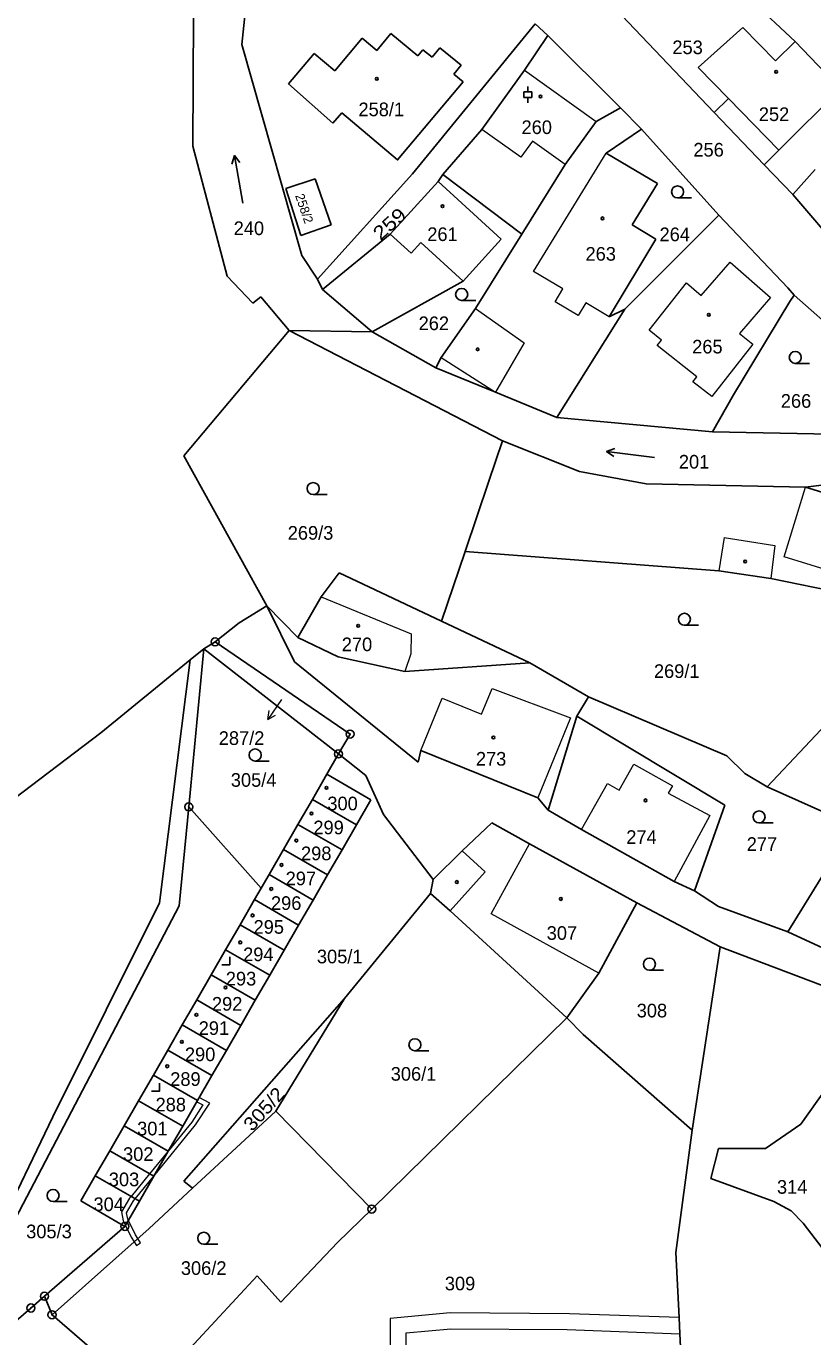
# Model space of a CAD drawing. Extents: x -727701 to -724405, y -960481 to -957284.
# Drawn here: x -727055.1 to -726957, y -958124 to -957960.6 of the extents above; entities that cross this region are included whole.
import ezdxf
from ezdxf.enums import TextEntityAlignment as Align

# ---------------------------------------------------------------- set-up
doc = ezdxf.new("R2010")
doc.units = 0
doc.header["$LTSCALE"] = 0.68
for name, color, linetype, lineweight in [('1', 7, 'Continuous', 25), ('13', 7, 'Continuous', 13), ('3', 7, 'Continuous', 25), ('4', 7, 'Continuous', 13), ('5', 7, 'Continuous', 25), ('7', 7, 'Continuous', 13), ('8', 7, 'Continuous', 25)]:
    doc.layers.add(name, color=color, linetype=linetype, lineweight=lineweight)
doc.layers.add('2', color=7, linetype='Continuous')

msp = doc.modelspace()

# ---------------------------------------------------------------- linework, layer by layer
at = {"layer": '1'}
for p, q in [((-727027.33, -957954.13), (-727028.21, -957962.91)), ((-726982.51, -957957.55), (-726969.33, -957971.38)), ((-726959.21, -957962.52), (-726964.74, -957957.39)), ((-727034.33, -957975.58), (-727034.25, -957959.25)), ((-727006.95, -957979.03), (-726991.64, -957960.34)), ((-726990.05, -957961.81), (-726991.64, -957960.34)), ((-727016.64, -957966.2), (-727013.22, -957962.12)), ((-727013.22, -957962.12), (-727011.39, -957963.67)), ((-727011.39, -957963.67), (-727009.64, -957961.55)), ((-727009.64, -957961.55), (-727006.26, -957964.34)), ((-726992.98, -957966.1), (-726990.05, -957961.81)), ((-726981, -957970.8), (-726990.05, -957961.81)), ((-726965.77, -957960.81), (-726971.31, -957965.77)), ((-726961.7, -957964.96), (-726965.77, -957960.81)), ((-727028.21, -957962.91), (-727020.72, -957989.23)), ((-727006.26, -957964.34), (-727005.64, -957963.56)), ((-727005.64, -957963.56), (-727004.47, -957964.49)), ((-727004.47, -957964.49), (-727003.54, -957963.33)), ((-727003.54, -957963.33), (-727000.86, -957965.47)), ((-726959.21, -957962.52), (-726961.7, -957964.96)), ((-726953.58, -957968.43), (-726959.21, -957962.52)), ((-727022.4, -957967.83), (-727019.21, -957964.04)), ((-727019.21, -957964.04), (-727016.64, -957966.2)), ((-727000.86, -957965.47), (-727001.79, -957966.63)), ((-727001.79, -957966.63), (-727000.63, -957967.56)), ((-726998.28, -957973.5), (-726992.98, -957966.1)), ((-726971.31, -957965.77), (-726967.55, -957969.64)), ((-727016.86, -957972.73), (-727022.4, -957967.83)), ((-726961.28, -957976.08), (-726953.58, -957968.43)), ((-726967.55, -957969.64), (-726969.33, -957971.38)), ((-727015.77, -957971.44), (-727016.86, -957972.73)), ((-726984.04, -957972.51), (-726981, -957970.8)), ((-726978.4, -957973.45), (-726981, -957970.8)), ((-726969.33, -957971.38), (-726963.11, -957977.91)), ((-727003.15, -957979.12), (-726998.28, -957973.5)), ((-726987.89, -957977.89), (-726984.04, -957972.51)), ((-726982.79, -957976.48), (-726978.4, -957973.45)), ((-726968.75, -957984.19), (-726978.4, -957973.45)), ((-727030.04, -957991.79), (-727034.33, -957975.58)), ((-726976.41, -957980.24), (-726982.79, -957976.48)), ((-726963.11, -957977.91), (-726961.28, -957976.08)), ((-726993.3, -957986.57), (-726987.89, -957977.89)), ((-726963.11, -957977.91), (-726959.51, -957981.63)), ((-727022.75, -957980.85), (-727019.06, -957979.65)), ((-727019.06, -957979.65), (-727017.1, -957985.39)), ((-727018.8, -957992.19), (-727006.95, -957979.03)), ((-727009.74, -957986.55), (-727003.76, -957979.99)), ((-727003.76, -957979.99), (-727003.15, -957979.12)), ((-726995.87, -957987.2), (-727003.76, -957979.99)), ((-727003.15, -957979.12), (-726993.3, -957986.57)), ((-726956.74, -957978.5), (-726959.51, -957981.63)), ((-727020.85, -957986.71), (-727022.75, -957980.85)), ((-726979.56, -957985.41), (-726976.41, -957980.24)), ((-726959.51, -957981.63), (-726950.42, -957992.25)), ((-726980.45, -957995.91), (-726968.75, -957984.19)), ((-726960.13, -957993.26), (-726968.75, -957984.19)), ((-727017.1, -957985.39), (-727020.85, -957986.71)), ((-727018.15, -957993.47), (-727009.74, -957986.55)), ((-726999.07, -957995.83), (-726993.3, -957986.57)), ((-726976.62, -957987.17), (-726979.56, -957985.41)), ((-727000.62, -957992.41), (-726995.87, -957987.2)), ((-726982.41, -957996.85), (-726976.62, -957987.17)), ((-727020.72, -957989.23), (-727018.8, -957992.19)), ((-727026.83, -957995.18), (-727030.04, -957991.79)), ((-727018.8, -957992.19), (-727018.15, -957993.47)), ((-727011.98, -957998.72), (-727000.62, -957992.41)), ((-727025.84, -957994.37), (-727026.83, -957995.18)), ((-727022.34, -957998.59), (-727025.84, -957994.37)), ((-727018.15, -957993.47), (-727011.98, -957998.72)), ((-726959.34, -957994.18), (-726960.13, -957993.26)), ((-726959.88, -957994.94), (-726959.34, -957994.18)), ((-726959.34, -957994.18), (-726949.18, -958003.2)), ((-727003.38, -958001.95), (-726999.07, -957995.83)), ((-726988.96, -958009.41), (-726980.45, -957995.91)), ((-726980.45, -957995.91), (-726982.41, -957996.85)), ((-726966.9, -958006.6), (-726959.88, -957994.94)), ((-727035.47, -958014.18), (-727022.34, -957998.59)), ((-727022.34, -957998.59), (-726995.72, -958012.31)), ((-727022.34, -957998.59), (-727011.98, -957998.72)), ((-727011.98, -957998.72), (-727004.05, -958003.22)), ((-727004.05, -958003.22), (-727003.38, -958001.95)), ((-727004.05, -958003.22), (-726996.59, -958006.28)), ((-726996.59, -958006.28), (-726988.96, -958009.41)), ((-726969.55, -958011.22), (-726966.9, -958006.6)), ((-726988.96, -958009.41), (-726969.55, -958011.22)), ((-726995.72, -958012.31), (-726997.43, -958017.36)), ((-726995.72, -958012.31), (-726986.13, -958016.16)), ((-726969.55, -958011.22), (-726954.77, -958011.5)), ((-727025.11, -958032.9), (-727035.47, -958014.18)), ((-726997.43, -958017.36), (-727000.39, -958026.11)), ((-726986.13, -958016.16), (-726977.8, -958017.71)), ((-726957.94, -958018.11), (-726942.44, -958016.08)), ((-726977.8, -958017.71), (-726957.94, -958018.11)), ((-726945.74, -958021.85), (-726957.94, -958018.11)), ((-727000.39, -958026.11), (-727003.33, -958034.81)), ((-726968.75, -958028.55), (-727000.39, -958026.11)), ((-727018.35, -958031.77), (-727016.1, -958028.8)), ((-727016.1, -958028.8), (-727003.33, -958034.81)), ((-726968.75, -958028.55), (-726962.25, -958029.5)), ((-726962.25, -958029.5), (-726950.05, -958032)), ((-727021.23, -958036.86), (-727018.35, -958031.77)), ((-727028.57, -958035.03), (-727025.11, -958032.9)), ((-727025.11, -958032.9), (-727021.23, -958036.86)), ((-727021.65, -958039.9), (-727025.11, -958032.9)), ((-727028.57, -958035.03), (-727031.55, -958037.4)), ((-727003.33, -958034.81), (-726992.3, -958040)), ((-727021.23, -958036.86), (-727016.19, -958039.26)), ((-727032.95, -958038.25), (-727034.84, -958057.97)), ((-727034.66, -958039.64), (-727032.95, -958038.25)), ((-727032.95, -958038.25), (-727031.55, -958037.4)), ((-727016.18, -958051.37), (-727032.95, -958038.25)), ((-727031.55, -958037.4), (-727014.73, -958048.89)), ((-726962.73, -958055.45), (-726946.89, -958038.61)), ((-727045.8, -958048.73), (-727034.66, -958039.64)), ((-727038.49, -958069.94), (-727034.66, -958039.64)), ((-727006.24, -958052.4), (-727021.65, -958039.9)), ((-727016.19, -958039.26), (-727007.91, -958041.08)), ((-727007.91, -958041.08), (-726992.3, -958040)), ((-726992.3, -958040), (-726984.99, -958044.25)), ((-726986.46, -958046.64), (-726984.99, -958044.25)), ((-726984.99, -958044.25), (-726967.76, -958051.62)), ((-726990.02, -958058.36), (-726986.46, -958046.64)), ((-726986.46, -958046.64), (-726967.99, -958057.74)), ((-727080.39, -958074.95), (-727045.8, -958048.73)), ((-727014.73, -958048.89), (-727016.18, -958051.37)), ((-727016.18, -958051.37), (-727017.64, -958053.88)), ((-727012.76, -958054.04), (-727016.18, -958051.37)), ((-727005.9, -958050.92), (-727006.24, -958052.4)), ((-726991.32, -958056.85), (-727005.9, -958050.92)), ((-726967.76, -958051.62), (-726965.5, -958053.82)), ((-727019.42, -958057.03), (-727017.64, -958053.88)), ((-727017.64, -958053.88), (-727012.12, -958057.08)), ((-727010.57, -958058.93), (-727012.76, -958054.04)), ((-726965.5, -958053.82), (-726962.73, -958055.45)), ((-726990.02, -958058.36), (-726991.32, -958056.85)), ((-726962.73, -958055.45), (-726953.06, -958059.81)), ((-727036.02, -958070.29), (-727034.84, -958057.97)), ((-727034.84, -958057.97), (-727025.81, -958068.11)), ((-727021.23, -958060.16), (-727019.42, -958057.03)), ((-727013.93, -958060.2), (-727019.42, -958057.03)), ((-727012.12, -958057.08), (-727013.93, -958060.2)), ((-726985.87, -958060.8), (-726990.02, -958058.36)), ((-726971.8, -958068.45), (-726967.99, -958057.74)), ((-727023.03, -958063.28), (-727021.23, -958060.16)), ((-727015.73, -958063.33), (-727021.23, -958060.16)), ((-727010.57, -958058.93), (-727004.36, -958067.03)), ((-726997.07, -958059.97), (-727000.76, -958063.46)), ((-726992.34, -958062.57), (-726997.07, -958059.97)), ((-727013.93, -958060.2), (-727015.73, -958063.33)), ((-726974.3, -958067.28), (-726985.87, -958060.8)), ((-727024.83, -958066.41), (-727023.03, -958063.28)), ((-727017.53, -958066.45), (-727023.03, -958063.28)), ((-727015.73, -958063.33), (-727017.53, -958066.45)), ((-726978.96, -958069.95), (-726992.34, -958062.57)), ((-727000.76, -958063.46), (-727004.36, -958067.03)), ((-726960.13, -958073.56), (-726954.24, -958063.98)), ((-727024.83, -958066.41), (-727025.81, -958068.11)), ((-727019.33, -958069.58), (-727024.83, -958066.41)), ((-727017.53, -958066.45), (-727019.33, -958069.58)), ((-727026.63, -958069.53), (-727025.81, -958068.11)), ((-727004.36, -958067.03), (-727004.71, -958068.75)), ((-726971.8, -958068.45), (-726974.3, -958067.28)), ((-727051.8, -958096.6), (-727038.49, -958069.94)), ((-727028.44, -958072.66), (-727026.63, -958069.53)), ((-727021.14, -958072.7), (-727026.63, -958069.53)), ((-727019.33, -958069.58), (-727021.14, -958072.7)), ((-727004.71, -958068.75), (-727015.4, -958081.85)), ((-727004.71, -958068.75), (-727002.26, -958070.94)), ((-726978.96, -958069.95), (-726983.73, -958078.71)), ((-726968.6, -958075.4), (-726978.96, -958069.95)), ((-726968.78, -958070.41), (-726971.8, -958068.45)), ((-727057.36, -958111.03), (-727036.02, -958070.29)), ((-727002.26, -958070.94), (-726987.71, -958084.26)), ((-726960.13, -958073.56), (-726968.78, -958070.41)), ((-727030.24, -958075.78), (-727028.44, -958072.66)), ((-727022.94, -958075.83), (-727028.44, -958072.66)), ((-727021.14, -958072.7), (-727022.94, -958075.83)), ((-726954.11, -958076.32), (-726960.13, -958073.56)), ((-727032.04, -958078.91), (-727030.24, -958075.78)), ((-727024.74, -958078.95), (-727030.24, -958075.78)), ((-727022.94, -958075.83), (-727024.74, -958078.95)), ((-726968.6, -958075.4), (-726972.09, -958098.29)), ((-726951.25, -958082), (-726968.6, -958075.4)), ((-727033.85, -958082.04), (-727032.04, -958078.91)), ((-727026.54, -958082.08), (-727032.04, -958078.91)), ((-727024.74, -958078.95), (-727026.54, -958082.08)), ((-726983.73, -958078.71), (-726987.71, -958084.26)), ((-727035.65, -958085.16), (-727033.85, -958082.04)), ((-727015.4, -958081.85), (-727035.46, -958104.63)), ((-727028.35, -958085.21), (-727033.85, -958082.04)), ((-727026.54, -958082.08), (-727028.35, -958085.21)), ((-727015.4, -958081.85), (-727024, -958095.9)), ((-727012.03, -958108.11), (-726987.71, -958084.26)), ((-726987.71, -958084.26), (-726985.65, -958086.34)), ((-727037.45, -958088.29), (-727035.65, -958085.16)), ((-727030.15, -958088.33), (-727035.65, -958085.16)), ((-727028.35, -958085.21), (-727030.15, -958088.33)), ((-726985.65, -958086.34), (-726972.09, -958098.29)), ((-726951.61, -958087.78), (-726958.52, -958097.51)), ((-727039.25, -958091.41), (-727037.45, -958088.29)), ((-727031.95, -958091.46), (-727037.45, -958088.29)), ((-727030.15, -958088.33), (-727031.95, -958091.46)), ((-727041.09, -958094.6), (-727039.25, -958091.41)), ((-727033.76, -958094.58), (-727039.25, -958091.41)), ((-727031.95, -958091.46), (-727033.76, -958094.58)), ((-727042.89, -958097.72), (-727041.09, -958094.6)), ((-727035.59, -958097.77), (-727041.09, -958094.6)), ((-727033.76, -958094.58), (-727035.59, -958097.77)), ((-727024, -958095.9), (-727034.36, -958105.5)), ((-727024, -958095.9), (-727012.03, -958108.11)), ((-727063.3, -958120.4), (-727051.8, -958096.6)), ((-727044.7, -958100.85), (-727042.89, -958097.72)), ((-727037.4, -958100.89), (-727042.89, -958097.72)), ((-726958.52, -958097.51), (-726962.94, -958100.56)), ((-727035.59, -958097.77), (-727037.4, -958100.89)), ((-726972.09, -958098.29), (-726974.09, -958113.52)), ((-727046.5, -958103.97), (-727044.7, -958100.85)), ((-727039.2, -958104.02), (-727044.7, -958100.85)), ((-727037.4, -958100.89), (-727039.2, -958104.02)), ((-726968.8, -958100.56), (-726969.73, -958104.32)), ((-726962.94, -958100.56), (-726968.8, -958100.56)), ((-727048.3, -958107.1), (-727046.5, -958103.97)), ((-727041, -958107.15), (-727046.5, -958103.97)), ((-727039.2, -958104.02), (-727041, -958107.15)), ((-727034.36, -958105.5), (-727039.78, -958110.52)), ((-727035.46, -958104.63), (-727034.36, -958105.5)), ((-726969.73, -958104.32), (-726961.88, -958107.17)), ((-727042.8, -958110.27), (-727048.3, -958107.1)), ((-727041, -958107.15), (-727042.8, -958110.27)), ((-726961.88, -958107.17), (-726959.71, -958108.33)), ((-727012.03, -958108.11), (-727016.3, -958112.3)), ((-726959.71, -958108.33), (-726958.25, -958109.88)), ((-727052.83, -958118.99), (-727042.8, -958110.27)), ((-727039.78, -958110.52), (-727051.89, -958121.3)), ((-726958.25, -958109.88), (-726940.92, -958132.54)), ((-727023.36, -958119.73), (-727016.3, -958112.3)), ((-727026.33, -958116.42), (-727039.81, -958130.97)), ((-727026.33, -958116.42), (-727023.36, -958119.73)), ((-727054.52, -958120.45), (-727052.83, -958118.99)), ((-727051.89, -958121.3), (-727052.83, -958118.99)), ((-727056.99, -958122.6), (-727054.52, -958120.45)), ((-727051.89, -958121.3), (-727040.17, -958131.4))]:
    msp.add_line(p, q, dxfattribs=at)
for points in [[(-727000.63, -957967.56), (-727008.8, -957977.31), (-727015.77, -957971.44)], [(-726973.24, -958131.06), (-726973.6, -958123.65), (-726973.7, -958121.64), (-726974.09, -958113.52)]]:
    msp.add_lwpolyline(points, dxfattribs=at)
at = {"layer": '13'}
for points in [[(-727042, -958111.62), (-727041.64, -958112.18), (-727041.19, -958111.78), (-727041.48, -958111.32), (-727042.37, -958109.53), (-727042.44, -958109.39), (-727042.6, -958108.58), (-727041.71, -958107.1), (-727041.51, -958106.85), (-727039.2, -958104.02), (-727033.98, -958097.62), (-727032.23, -958094.89), (-727033.55, -958094.21), (-727033.76, -958094.58), (-727033.85, -958094.73), (-727033.09, -958095.13), (-727034.46, -958097.26), (-727037.4, -958100.89), (-727039.72, -958103.72), (-727042.04, -958106.55), (-727042.21, -958106.76), (-727043.24, -958108.46), (-727043.02, -958109.59), (-727042.73, -958110.15)], [(-727041.64, -958112.18), (-727041.34, -958112.66), (-727040.84, -958112.34), (-727041.19, -958111.78)], [(-727008.18, -958128.17), (-727007.7, -958128.17), (-727007.73, -958123.56), (-727002.18, -958123.04), (-726987.65, -958123.15), (-726973.6, -958123.65), (-726973.7, -958121.64), (-726987.35, -958121.16), (-727002.26, -958121.04), (-727009.73, -958121.74), (-727009.72, -958125.38), (-727017.64, -958125.47), (-727017.59, -958127.64), (-727008.25, -958127.54)]]:
    msp.add_lwpolyline(points, close=True, dxfattribs=at)
at = {"layer": '3'}
for p, q in [((-726992.55, -957968.831), (-726992.55, -957968.16)), ((-726993.053, -957968.831), (-726992.047, -957968.831)), ((-726993.053, -957969.502), (-726993.053, -957968.831)), ((-726993.053, -957969.502), (-726992.047, -957969.502)), ((-726992.55, -957970.17), (-726992.55, -957969.502)), ((-726992.047, -957969.502), (-726992.047, -957968.831)), ((-727029.145, -957976.767), (-727028.482, -957977.642)), ((-726973.893, -957982.04), (-726972.143, -957982.04)), ((-727000.813, -957994.82), (-726999.063, -957994.82)), ((-726959.213, -958002.67), (-726957.463, -958002.67)), ((-726982.744, -958013.674), (-726981.713, -958013.295)), ((-727019.323, -958019.03), (-727017.573, -958019.03)), ((-726973.043, -958035.33), (-726971.293, -958035.33)), ((-727026.563, -958052.25), (-727024.813, -958052.25)), ((-726963.733, -958059.97), (-726961.983, -958059.97)), ((-726977.403, -958078.33), (-726975.653, -958078.33)), ((-727006.643, -958088.37), (-727004.893, -958088.37)), ((-727051.763, -958107.17), (-727050.013, -958107.17)), ((-727032.973, -958112.5), (-727031.223, -958112.5))]:
    msp.add_line(p, q, dxfattribs=at)
for points in [[(-727028.104, -957982.676), (-727029.145, -957976.767), (-727029.47, -957977.817)], [(-726976.788, -958014.405), (-726982.744, -958013.674), (-726981.835, -958014.291)], [(-727030.731, -958077.65), (-727029.73, -958077.65), (-727029.73, -958076.65)], [(-727039.501, -958093.43), (-727038.5, -958093.43), (-727038.5, -958092.43)]]:
    msp.add_lwpolyline(points, dxfattribs=at)
for centre in [(-726973.8929, -957981.2898), (-727000.8129, -957994.0698), (-726959.2129, -958001.9198), (-727019.3229, -958018.2798), (-726973.0429, -958034.5798), (-727026.5629, -958051.4998), (-726963.7329, -958059.2198), (-726977.4029, -958077.5798), (-727006.6429, -958087.6198), (-727051.7629, -958106.4198), (-727032.9729, -958111.7498)]:
    msp.add_circle(centre, 0.75, dxfattribs=at)
at = {"layer": '4'}
for p, q in [((-726992.98, -957966.1), (-726984.04, -957972.51)), ((-726961.28, -957976.08), (-726967.55, -957969.64)), ((-726993.43, -957976.98), (-726998.28, -957973.5)), ((-726991.99, -957974.96), (-726993.43, -957976.98)), ((-726987.89, -957977.89), (-726991.99, -957974.96)), ((-726991.84, -957991.21), (-726982.79, -957976.48)), ((-727007.12, -957988.92), (-727009.74, -957986.55)), ((-727005.91, -957987.58), (-727007.12, -957988.92)), ((-727000.62, -957992.41), (-727005.91, -957987.58)), ((-726988.19, -957993.39), (-726991.84, -957991.21)), ((-726970.94, -957994.22), (-726967.34, -957990.07)), ((-726967.34, -957990.07), (-726962.29, -957994.45)), ((-726977.45, -957998.55), (-726972.76, -957992.64)), ((-726972.76, -957992.64), (-726970.94, -957994.22)), ((-726989.15, -957995), (-726988.19, -957993.39)), ((-726962.29, -957994.45), (-726966.18, -957998.96)), ((-726999.07, -957995.83), (-726993, -958000.11)), ((-726986.28, -957996.72), (-726989.15, -957995)), ((-726985.31, -957995.11), (-726986.28, -957996.72)), ((-726982.41, -957996.85), (-726985.31, -957995.11)), ((-726975.89, -957999.79), (-726977.45, -957998.55)), ((-726966.18, -957998.96), (-726964.49, -958000.29)), ((-726993, -958000.11), (-726996.59, -958006.28)), ((-726976.42, -958000.46), (-726975.89, -957999.79)), ((-726971.48, -958004.33), (-726976.42, -958000.46)), ((-726964.49, -958000.29), (-726969.61, -958006.82)), ((-727003.38, -958001.95), (-726996.59, -958006.28)), ((-726971.98, -958004.96), (-726971.48, -958004.33)), ((-726969.61, -958006.82), (-726971.98, -958004.96)), ((-726960.6, -958026.79), (-726957.94, -958018.11)), ((-726968.1, -958024.4), (-726968.75, -958028.55)), ((-726968.1, -958024.4), (-726961.75, -958025.38)), ((-726961.75, -958025.38), (-726962.25, -958029.5)), ((-726953.85, -958028.86), (-726960.6, -958026.79)), ((-727007.16, -958038.88), (-727007.91, -958041.08)), ((-726998.32, -958046.41), (-726997.02, -958043.21)), ((-726997.02, -958043.21), (-726987.25, -958046.86)), ((-727005.9, -958050.92), (-727003.24, -958044.43)), ((-727003.24, -958044.43), (-726998.32, -958046.41)), ((-726987.25, -958046.86), (-726991.32, -958056.85)), ((-726981.16, -958055.9), (-726979.35, -958052.65)), ((-726979.35, -958052.65), (-726974.53, -958055.35)), ((-726985.87, -958060.8), (-726982.65, -958055.06)), ((-726982.65, -958055.06), (-726981.16, -958055.9)), ((-726974.53, -958055.35), (-726975.05, -958056.27)), ((-726975.05, -958056.27), (-726969.88, -958059.04)), ((-726969.88, -958059.04), (-726974.3, -958067.28)), ((-726997.15, -958071.3), (-726992.34, -958062.57)), ((-727000.76, -958063.46), (-726997.88, -958066.06)), ((-726997.88, -958066.06), (-727002.26, -958070.94)), ((-726983.73, -958078.71), (-726997.15, -958071.3))]:
    msp.add_line(p, q, dxfattribs=at)
msp.add_lwpolyline([(-727018.35, -958031.77), (-727007.11, -958036.4), (-727007.16, -958038.88)], dxfattribs=at)
at = {"layer": '5'}
for centre in [(-727011.3968, -957967.1892), (-726961.6068, -957966.3092), (-726990.9868, -957969.3992), (-727003.1968, -957983.0792), (-726983.2568, -957984.5892), (-726970.0068, -957996.6192), (-726998.8168, -958000.9192), (-726965.4668, -958027.3692), (-727013.7168, -958035.3892), (-726996.8568, -958049.3192), (-727017.6768, -958055.5892), (-726977.8868, -958057.1592), (-727019.5368, -958058.7892), (-727021.4268, -958062.1792), (-727023.2668, -958065.2092), (-727024.5468, -958068.1992), (-727001.4068, -958067.3392), (-726988.4468, -958069.4492), (-727026.8768, -958071.4992), (-727028.4168, -958074.8592), (-727030.2468, -958080.4892), (-727033.8868, -958083.8992), (-727035.6968, -958087.2692), (-727037.5168, -958090.3092)]:
    msp.add_circle(centre, 0.175, dxfattribs=at)
at = {"layer": '7'}
msp.add_line((-727024.991, -958047.058), (-727024.007, -958046.525), dxfattribs=at)
msp.add_lwpolyline([(-727023.27, -958044.6), (-727024.991, -958047.058), (-727024.827, -958045.951)], dxfattribs=at)
at = {"layer": '8'}
for centre, radius in [((-727031.55, -958037.3999), 0.5), ((-727031.55, -958037.3999), 0.0303), ((-727014.73, -958048.8899), 0.5), ((-727014.73, -958048.8899), 0.0303), ((-727016.18, -958051.3699), 0.5), ((-727016.18, -958051.3699), 0.0303), ((-727034.84, -958057.9699), 0.5), ((-727034.84, -958057.9699), 0.0303), ((-727012.03, -958108.1099), 0.5), ((-727012.03, -958108.1099), 0.0303), ((-727042.8, -958110.2699), 0.5), ((-727042.8, -958110.2699), 0.0303), ((-727052.83, -958118.9899), 0.5), ((-727052.83, -958118.9899), 0.0303), ((-727054.52, -958120.4499), 0.5), ((-727054.52, -958120.4499), 0.0303), ((-727051.89, -958121.2999), 0.5), ((-727051.89, -958121.2999), 0.0303)]:
    msp.add_circle(centre, radius, dxfattribs=at)

# ---------------------------------------------------------------- texts
at = {"layer": '2'}
for s, p in [('253', (-726974.54, -957964.115)), ('258/1', (-727013.68, -957971.855)), ('252', (-726963.76, -957972.455)), ('260', (-726993.35, -957974.075)), ('256', (-726971.92, -957976.885)), ('240', (-727029.24, -957986.675)), ('261', (-727005.1, -957987.415)), ('264', (-726976.14, -957987.435)), ('263', (-726985.37, -957989.865)), ('262', (-727006.18, -957998.525)), ('265', (-726972.07, -958001.435)), ('266', (-726961.02, -958008.205)), ('201', (-726973.73, -958015.785)), ('269/3', (-727022.5, -958024.655)), ('270', (-727015.76, -958038.555)), ('269/1', (-726976.84, -958041.895)), ('273', (-726999.04, -958052.825)), ('300', (-727017.56, -958058.395)), ('299', (-727019.3, -958061.385)), ('274', (-726980.29, -958062.585)), ('277', (-726965.27, -958063.455)), ('298', (-727020.84, -958064.615)), ('297', (-727022.76, -958067.745)), ('296', (-727024.59, -958070.815)), ('295', (-727026.76, -958073.785)), ('307', (-726990.21, -958074.545)), ('294', (-727028.06, -958077.205)), ('305/1', (-727018.86, -958077.475)), ('293', (-727030.22, -958080.235)), ('292', (-727031.95, -958083.375)), ('308', (-726978.99, -958084.215)), ('291', (-727033.6, -958086.405)), ('290', (-727035.32, -958089.675)), ('289', (-727037.15, -958092.755)), ('288', (-727038.98, -958095.935)), ('314', (-726961.5, -958106.205)), ('305/3', (-727055.11, -958111.755)), ('309', (-727002.91, -958118.245))]:
    msp.add_text(s, height=1.7, dxfattribs=at).set_placement(p)
msp.add_text('258/2', height=1.139, rotation=289, dxfattribs=at).set_placement((-727020.9758, -957983.5471), align=Align.CENTER)
for s, rotation, width, p in [('259', 42, 1.2, (-727010.935, -957987.425)), ('305/2', 48, 1.1, (-727026.924, -958098.534))]:
    msp.add_text(s, height=1.7, rotation=rotation, dxfattribs=dict(at, width=width)).set_placement(p)
msp.add_text('287/2', height=1.7, dxfattribs=at).set_placement((-727025.41, -958050.245), align=Align.RIGHT)
for s, p in [('305/4', (-727026.75, -958055.465)), ('306/1', (-727006.81, -958092.105)), ('301', (-727039.379, -958098.925)), ('302', (-727041.139, -958102.115)), ('303', (-727042.909, -958105.265)), ('304', (-727044.819, -958108.365)), ('306/2', (-727032.98, -958116.325))]:
    msp.add_text(s, height=1.7, dxfattribs=at).set_placement(p, align=Align.CENTER)

doc.saveas('drawing.dxf')
